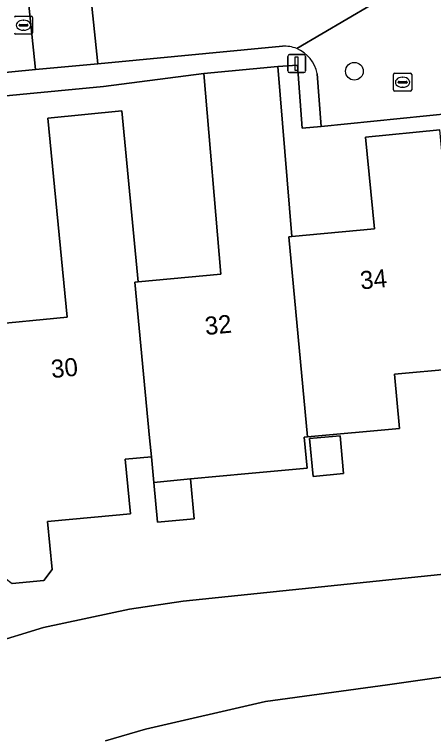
# Model space of a CAD drawing. Extents: x 157793 to 159380, y 380877 to 382313.
# Drawn here: x 158456.61 to 158479.78, y 381160.97 to 381201.1 of the extents above; entities that cross this region are included whole.
import ezdxf

# ---------------------------------------------------------------- set-up
doc = ezdxf.new("R2010")
doc.units = 0
for name, color, linetype in [('IMGEO_Boom', 7, 'Continuous'), ('IMGEO_Damwand', 7, 'Continuous'), ('IMGEO_Erf', 7, 'Continuous'), ('IMGEO_Kolk', 7, 'Continuous'), ('IMGEO_Lichtmast', 7, 'Continuous'), ('IMGEO_Oever', 7, 'Continuous'), ('IMGEO_Pand', 7, 'Continuous'), ('IMGEO_Pand_nummerreeks', 7, 'Continuous'), ('IMGEO_Rijbaan_lokaal_open', 7, 'Continuous'), ('IMGEO_Rioolput', 7, 'Continuous'), ('IMGEO_Voetpad_open', 7, 'Continuous'), ('IMGEO_Waterloop', 7, 'Continuous')]:
    doc.layers.add(name, color=color, linetype=linetype)

msp = doc.modelspace()

# ---------------------------------------------------------------- linework, layer by layer
at = {"layer": 'IMGEO_Boom'}
msp.add_circle((158475.406, 381197.963), 0.489, dxfattribs=at)
at = {"layer": 'IMGEO_Damwand'}
msp.add_lwpolyline([(158491.779, 381166.123), (158477.231, 381164.035), (158470.485, 381163.113), (158463.848, 381161.591), (158461.647, 381160.946)], dxfattribs=at)
at = {"layer": 'IMGEO_Erf'}
for points in [[(158437.246, 381160.472), (158442.422, 381162.212), (158448.623, 381164.199), (158450.965, 381164.837), (158455.184, 381166.285), (158458.213, 381167.208), (158462.978, 381168.229), (158465.934, 381168.665), (158482.116, 381170.34), (158494.752, 381172.28), (158498.036, 381172.994), (158500.751, 381174.141), (158502.381, 381175.376), (158503.675, 381176.792), (158504.257, 381177.69), (158505.004, 381179.524), (158505.458, 381182.578), (158505.469, 381183.437), (158505.318, 381184.258), (158502.748, 381197.597), (158500.66, 381208.431)], [(158496.878, 381197.276), (158473.576, 381194.917), (158472.526, 381194.816), (158472.258, 381198.299), (158471.171, 381198.233), (158471.945, 381188.823), (158476.529, 381189.26), (158476.029, 381194.323), (158480.125, 381194.73)], [(158454.952, 381183.935), (158459.521, 381184.373), (158458.457, 381195.374), (158462.539, 381195.771), (158463.458, 381186.315), (158468.027, 381186.753), (158467.081, 381197.838), (158461.541, 381197.122), (158445.123, 381195.558)], [(158480.881, 381181.507), (158477.629, 381181.214), (158477.899, 381178.212), (158472.812, 381177.754), (158472.636, 381177.738), (158472.791, 381176.016), (158469.545, 381175.717), (158466.353, 381175.423), (158466.556, 381173.218), (158464.525, 381173.031), (158464.317, 381175.236), (158464.184, 381176.648), (158462.736, 381176.514), (158463.02, 381173.501), (158461.031, 381173.318), (158458.442, 381173.08), (158458.697, 381170.42), (158458.234, 381169.806), (158456.474, 381169.644)]]:
    msp.add_lwpolyline(points, dxfattribs=at)
msp.add_lwpolyline([(158473.125, 381175.563), (158472.932, 381177.664), (158474.618, 381177.816), (158474.811, 381175.719)], close=True, dxfattribs=at)
at = {"layer": 'IMGEO_Kolk'}
for p, q in [((158456.686, 381201.007), (158457.538, 381201.007)), ((158457.099, 381200.787), (158457.124, 381200.787)), ((158457.612, 381200.933), (158457.612, 381200.081)), ((158456.87, 381200.501), (158456.87, 381200.513)), ((158457.308, 381200.464), (158456.91, 381200.464)), ((158456.913, 381200.55), (158457.311, 381200.55)), ((158457.122, 381200.227), (158457.097, 381200.227)), ((158457.354, 381200.513), (158457.354, 381200.501)), ((158457.538, 381200.007), (158456.686, 381200.007))]:
    msp.add_line(p, q, dxfattribs=at)
for points in [[(158456.686, 381201.007), (158457.538, 381201.007)], [(158457.612, 381200.933), (158457.612, 381200.081)], [(158457.538, 381200.007), (158456.686, 381200.007)]]:
    msp.add_lwpolyline(points, dxfattribs=at)
for centre, radius, start, end in [((158456.688, 381200.931), 0.0765, 91.552, 178.448), ((158456.688, 381200.931), 0.0765, 91.552, 178.448), ((158457.536, 381200.931), 0.0765, 1.552, 88.448), ((158457.536, 381200.931), 0.0765, 1.552, 88.448), ((158456.91, 381200.51), 0.0403, 85.8775, 175.7526), ((158456.907, 381200.5), 0.0366, 178.938, 274.7102), ((158457.311, 381200.507), 0.043, 264.8664, 352.4533), ((158457.315, 381200.512), 0.0386, 1.7309, 96.639), ((158456.688, 381200.083), 0.0765, 181.552, 268.448), ((158456.688, 381200.083), 0.0765, 181.552, 268.448), ((158457.536, 381200.083), 0.0765, 271.552, 358.448), ((158457.536, 381200.083), 0.0765, 271.552, 358.448)]:
    msp.add_arc(centre, radius, start, end, dxfattribs=at)
for centre, major_axis, ratio, start_param, end_param in [((158457.098, 381200.507), (-0.387, 0.002), 0.722429, 4.712389, 7.853982), ((158457.123, 381200.507), (-0.39, 0.002), 0.717154, 1.570796, 4.712389)]:
    msp.add_ellipse(centre, major_axis=major_axis, ratio=ratio, start_param=start_param, end_param=end_param, dxfattribs=at)
at = {"layer": 'IMGEO_Lichtmast'}
for p, q in [((158471.719, 381197.985), (158471.719, 381198.785)), ((158471.719, 381198.785), (158471.719, 381197.985)), ((158471.819, 381198.885), (158472.609, 381198.885)), ((158472.609, 381198.885), (158471.819, 381198.885)), ((158472.709, 381198.785), (158472.709, 381197.985)), ((158472.709, 381197.985), (158472.709, 381198.785)), ((158472.609, 381197.885), (158471.819, 381197.885)), ((158471.819, 381197.885), (158472.609, 381197.885))]:
    msp.add_line(p, q, dxfattribs=at)
msp.add_lwpolyline([(158472.139, 381198.76), (158472.289, 381198.76), (158472.289, 381198.01), (158472.139, 381198.01), (158472.139, 381198.76)], dxfattribs=at)
for centre, start, end in [((158471.819, 381198.785), 90, 180), ((158471.819, 381198.785), 90, 180), ((158472.609, 381198.785), 0, 90), ((158472.609, 381198.785), 360, 90), ((158471.819, 381197.985), 180, 270), ((158471.819, 381197.985), 180, 270), ((158472.609, 381197.985), 270, 0), ((158472.609, 381197.985), 270, 0)]:
    msp.add_arc(centre, 0.1, start, end, dxfattribs=at)
at = {"layer": 'IMGEO_Oever'}
for points in [[(158500.66, 381208.431), (158502.748, 381197.597), (158505.318, 381184.258), (158505.469, 381183.437), (158505.458, 381182.578), (158505.004, 381179.524), (158504.257, 381177.69), (158503.675, 381176.792), (158502.381, 381175.376), (158500.751, 381174.141), (158498.036, 381172.994), (158494.752, 381172.28), (158482.116, 381170.34), (158465.934, 381168.665), (158462.978, 381168.229), (158458.213, 381167.208), (158455.184, 381166.285), (158450.965, 381164.837), (158448.623, 381164.199), (158442.422, 381162.212), (158437.246, 381160.472)], [(158461.647, 381160.946), (158463.848, 381161.591), (158470.485, 381163.113), (158477.231, 381164.035), (158491.779, 381166.123)]]:
    msp.add_lwpolyline(points, dxfattribs=at)
at = {"layer": 'IMGEO_Pand'}
for points in [[(158471.776, 381188.807), (158471.945, 381188.823), (158471.171, 381198.233), (158467.081, 381197.838), (158468.027, 381186.753), (158463.458, 381186.315), (158463.273, 381186.297), (158464.084, 381177.703), (158464.184, 381176.648), (158464.317, 381175.236), (158466.353, 381175.423), (158469.545, 381175.717), (158472.791, 381176.016), (158472.636, 381177.738), (158472.812, 381177.754)], [(158463.458, 381186.315), (158462.539, 381195.771), (158458.457, 381195.374), (158459.521, 381184.373), (158454.952, 381183.935), (158454.759, 381183.916), (158455.683, 381174.25), (158455.818, 381172.838), (158456.095, 381169.946), (158456.474, 381169.644), (158458.234, 381169.806), (158458.697, 381170.42), (158458.442, 381173.08), (158461.031, 381173.318), (158463.02, 381173.501), (158462.736, 381176.514), (158464.184, 381176.648), (158464.084, 381177.703), (158463.273, 381186.297)], [(158481.478, 381178.533), (158480.423, 381189.641), (158480.608, 381189.659), (158480.125, 381194.73), (158476.029, 381194.323), (158476.529, 381189.26), (158471.945, 381188.823), (158471.776, 381188.807), (158472.812, 381177.754), (158477.899, 381178.212), (158477.629, 381181.214), (158480.881, 381181.507), (158481.15, 381178.504)], [(158473.125, 381175.563), (158474.811, 381175.719), (158474.618, 381177.816), (158472.932, 381177.664)], [(158466.353, 381175.423), (158464.317, 381175.236), (158464.525, 381173.031), (158466.556, 381173.218)]]:
    msp.add_lwpolyline(points, close=True, dxfattribs=at)
at = {"layer": 'IMGEO_Rijbaan_lokaal_open'}
for points in [[(158472.924, 381204.592), (158470.963, 381204.292), (158460.708, 381203.357), (158461.221, 381198.372), (158471.433, 381199.347)], [(158472.219, 381199.216), (158479.141, 381203.293), (158479.008, 381204.618)], [(158441.66, 381196.48), (158457.774, 381198.055), (158457.257, 381203.058)], [(158479.141, 381203.293), (158472.219, 381199.216)], [(158473.341, 381197.829), (158473.576, 381194.917), (158496.878, 381197.276), (158496.358, 381202.643)]]:
    msp.add_lwpolyline(points, dxfattribs=at)
msp.add_lwpolyline([(158460.708, 381203.357), (158457.257, 381203.058), (158457.774, 381198.055), (158461.221, 381198.372)], close=True, dxfattribs=at)
for centre, radius, start, end in [((158471.533, 381197.526), 1.823, 67.917, 93.1584), ((158471.53, 381197.512), 1.838, 9.9423, 67.9993)]:
    msp.add_arc(centre, radius, start, end, dxfattribs=at)
at = {"layer": 'IMGEO_Rioolput'}
for p, q in [((158477.65, 381197.854), (158478.502, 381197.854)), ((158477.575, 381196.928), (158477.575, 381197.78)), ((158478.063, 381197.634), (158478.088, 381197.634)), ((158478.576, 381197.78), (158478.576, 381196.928)), ((158477.834, 381197.348), (158477.834, 381197.36)), ((158478.272, 381197.311), (158477.874, 381197.311)), ((158477.877, 381197.397), (158478.275, 381197.397)), ((158478.086, 381197.074), (158478.061, 381197.074)), ((158478.318, 381197.36), (158478.318, 381197.348)), ((158478.502, 381196.854), (158477.65, 381196.854))]:
    msp.add_line(p, q, dxfattribs=at)
for points in [[(158477.65, 381197.854), (158478.502, 381197.854)], [(158477.575, 381196.928), (158477.575, 381197.78)], [(158478.576, 381197.78), (158478.576, 381196.928)], [(158478.502, 381196.854), (158477.65, 381196.854)]]:
    msp.add_lwpolyline(points, dxfattribs=at)
for centre, radius, start, end in [((158477.652, 381197.778), 0.0765, 91.552, 178.448), ((158477.652, 381197.778), 0.0765, 91.552, 178.448), ((158478.5, 381197.778), 0.0765, 1.552, 88.448), ((158478.5, 381197.778), 0.0765, 1.552, 88.448), ((158477.874, 381197.357), 0.0403, 85.8775, 175.7526), ((158477.871, 381197.347), 0.0366, 178.938, 274.7102), ((158478.275, 381197.354), 0.043, 264.8664, 352.4533), ((158478.279, 381197.359), 0.0386, 1.7309, 96.639), ((158477.652, 381196.93), 0.0765, 181.552, 268.448), ((158477.652, 381196.93), 0.0765, 181.552, 268.448), ((158478.5, 381196.93), 0.0765, 271.552, 358.448), ((158478.5, 381196.93), 0.0765, 271.552, 358.448)]:
    msp.add_arc(centre, radius, start, end, dxfattribs=at)
for centre, major_axis, ratio, start_param, end_param in [((158478.062, 381197.354), (-0.387, 0.002), 0.722429, 4.712389, 7.853982), ((158478.087, 381197.354), (-0.39, 0.002), 0.717154, 1.570796, 4.712389)]:
    msp.add_ellipse(centre, major_axis=major_axis, ratio=ratio, start_param=start_param, end_param=end_param, dxfattribs=at)
at = {"layer": 'IMGEO_Voetpad_open'}
for points in [[(158471.433, 381199.347), (158461.221, 381198.372), (158457.774, 381198.055), (158441.66, 381196.48)], [(158435.998, 381188.28), (158428.505, 381185.406), (158425.292, 381184.147), (158382.725, 381167.434), (158380.022, 381166.386), (158374.1, 381164.032), (158345.684, 381144.763), (158345.336, 381148.653), (158349.465, 381151.46), (158344.919, 381151.126), (158343.198, 381150.791), (158343.94, 381142.482), (158373.758, 381162.728), (158437.204, 381187.562), (158441.151, 381194.476), (158445.198, 381194.878), (158445.123, 381195.558), (158461.541, 381197.122), (158467.081, 381197.838), (158471.171, 381198.233), (158472.258, 381198.299), (158472.526, 381194.816), (158473.576, 381194.917), (158473.341, 381197.829)]]:
    msp.add_lwpolyline(points, dxfattribs=at)
for centre, radius, start, end in [((158471.533, 381197.526), 1.823, 67.917, 93.1584), ((158471.53, 381197.512), 1.838, 9.9423, 67.9993)]:
    msp.add_arc(centre, radius, start, end, dxfattribs=at)
at = {"layer": 'IMGEO_Waterloop'}
msp.add_lwpolyline([(158491.779, 381166.123), (158477.231, 381164.035), (158470.485, 381163.113), (158463.848, 381161.591), (158461.647, 381160.946)], dxfattribs=at)

# ---------------------------------------------------------------- texts
at = {"layer": 'IMGEO_Pand_nummerreeks'}
for s, rotation, p in [('34', 5.5121, (158475.769, 381185.897)), ('32', 5.4775, (158467.183, 381183.377)), ('30', 5.4775, (158458.678, 381180.997))]:
    msp.add_text(s, height=1, rotation=rotation, dxfattribs=at).set_placement(p)

doc.saveas('drawing.dxf')
